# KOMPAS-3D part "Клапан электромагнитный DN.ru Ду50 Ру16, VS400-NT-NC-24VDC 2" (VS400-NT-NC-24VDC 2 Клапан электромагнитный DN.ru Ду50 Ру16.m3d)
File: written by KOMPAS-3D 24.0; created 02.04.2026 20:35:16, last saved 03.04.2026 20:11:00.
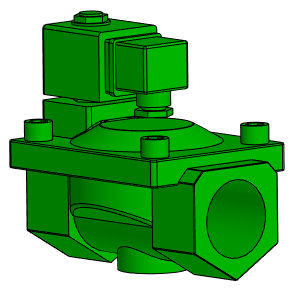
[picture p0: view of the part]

Document properties: Автор: artio; Полное имя файла: C:\Users\artio\OneDrive\Рабочий стол\Клапан электромагнитный DN.ru\VS400-NT-NC\VS400-NT-NC-24VDC 2 Клапан электромагнитный DN.ru Ду50 Ру16.m3d

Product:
- Body: Тело 1  | qty 1
    Масса: 7.119215
- Part/product: Клапан электромагнитный DN.ru Ду50 Ру16  | designation VS400-NT-NC-24VDC 2
    Масса: 3.509
    Раздел спецификации: Прочие изделия
    Примечание: D130-04731
    additional columns: ef56311e-7521-43dc-8291-0e6108b3d81d; VS400-ET-NC-220VAC 2; artio; c; Шероховатость не задана; Да

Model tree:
1. Операция без истории:1

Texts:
  VS400-NT-NC-24VDC 2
